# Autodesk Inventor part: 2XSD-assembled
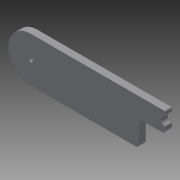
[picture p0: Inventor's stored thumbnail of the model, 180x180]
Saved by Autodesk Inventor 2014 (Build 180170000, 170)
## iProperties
Created: 2015-01
Part Number: 2XSD-assembled
Material: Generic
Document SubType Name: Modeling
Designer: Drano
Density: 1 g/cm^3
Appearance: Default
Author: Drano
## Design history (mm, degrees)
derived "2XSD.iam"
body "Solid1"
node "2XSD.ipt:1" dims "d0" = 10
node "backplate.ipt:1" dims "d0" = 10
node "2XSD.iam_Bodies" dims "d0" = 10
